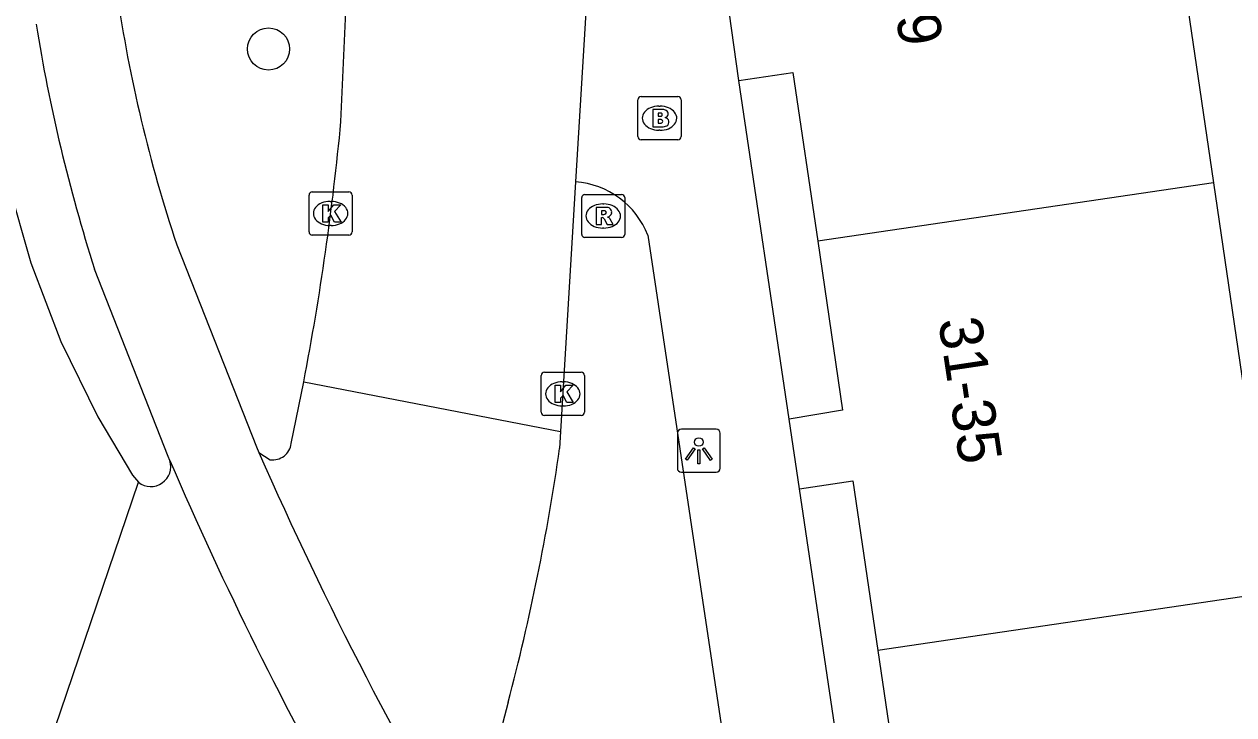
# Model space of a CAD drawing. Extents: x 159377 to 159983, y 382996 to 383595.
# Drawn here: x 159404.64 to 159432.72, y 383333.62 to 383349.64 of the extents above; entities that cross this region are included whole.
import ezdxf

# ---------------------------------------------------------------- set-up
doc = ezdxf.new("R2010")
doc.units = 0
for name, color, linetype in [('IMGEO_Boom', 7, 'Continuous'), ('IMGEO_Brandkraan', 7, 'Continuous'), ('IMGEO_Fietspad_open', 7, 'Continuous'), ('IMGEO_Kolk', 7, 'Continuous'), ('IMGEO_Lichtpunt', 7, 'Continuous'), ('IMGEO_Pand', 7, 'Continuous'), ('IMGEO_Pand_nummerreeks', 7, 'Continuous'), ('IMGEO_Rijbaan_lokaal_open', 7, 'Continuous'), ('IMGEO_Rijbaan_regionaal_gesloten', 7, 'Continuous'), ('IMGEO_Rioolput', 7, 'Continuous'), ('IMGEO_Voetpad_open', 7, 'Continuous')]:
    doc.layers.add(name, color=color, linetype=linetype)

msp = doc.modelspace()

# ---------------------------------------------------------------- linework, layer by layer
at = {"layer": 'IMGEO_Boom'}
msp.add_circle((159410.311, 383349.069), 0.489, dxfattribs=at)
at = {"layer": 'IMGEO_Brandkraan'}
for p, q in [((159418.886, 383347.038), (159418.886, 383347.89)), ((159418.961, 383347.964), (159419.813, 383347.964)), ((159419.374, 383347.744), (159419.399, 383347.744)), ((159419.887, 383347.89), (159419.887, 383347.038)), ((159419.397, 383347.184), (159419.372, 383347.184)), ((159419.813, 383346.964), (159418.961, 383346.964))]:
    msp.add_line(p, q, dxfattribs=at)
for points in [[(159418.886, 383347.038), (159418.886, 383347.89)], [(159418.961, 383347.964), (159419.813, 383347.964)], [(159419.887, 383347.89), (159419.887, 383347.038)], [(159419.234, 383347.664), (159419.234, 383347.264), (159419.447, 383347.264)], [(159419.465, 383347.664), (159419.234, 383347.664)], [(159419.413, 383347.583), (159419.359, 383347.583), (159419.359, 383347.507)], [(159419.359, 383347.507), (159419.412, 383347.507)], [(159419.421, 383347.431), (159419.359, 383347.431), (159419.359, 383347.35)], [(159419.359, 383347.35), (159419.421, 383347.35)], [(159419.813, 383346.964), (159418.961, 383346.964)]]:
    msp.add_lwpolyline(points, dxfattribs=at)
for centre, radius, start, end in [((159418.963, 383347.888), 0.0765, 91.552, 178.448), ((159418.963, 383347.888), 0.0765, 91.552, 178.448), ((159419.811, 383347.888), 0.0765, 1.552, 88.448), ((159419.811, 383347.888), 0.0765, 1.552, 88.448), ((159419.414, 383347.545), 0.0379, 267.8285, 90.9355), ((159419.469, 383347.519), 0.145, 59.4692, 91.5367), ((159419.494, 383347.566), 0.0922, 285.5137, 58.1501), ((159419.499, 383347.374), 0.105, 301.3115, 78.989), ((159419.422, 383347.39), 0.0404, 269.8759, 90.5077), ((159419.453, 383347.515), 0.251, 268.6676, 293.5347), ((159418.963, 383347.04), 0.0765, 181.552, 268.448), ((159418.963, 383347.04), 0.0765, 181.552, 268.448), ((159419.811, 383347.04), 0.0765, 271.552, 358.448), ((159419.811, 383347.04), 0.0765, 271.552, 358.448)]:
    msp.add_arc(centre, radius, start, end, dxfattribs=at)
for centre, major_axis, ratio, start_param, end_param in [((159419.373, 383347.464), (-0.387, 0.002), 0.722429, 4.712389, 7.853982), ((159419.398, 383347.464), (-0.39, 0.002), 0.717154, 1.570796, 4.712389)]:
    msp.add_ellipse(centre, major_axis=major_axis, ratio=ratio, start_param=start_param, end_param=end_param, dxfattribs=at)
at = {"layer": 'IMGEO_Fietspad_open'}
for points in [[(159408.182, 383344.528), (159410.03, 383339.844), (159410.089, 383339.709)], [(159408.022, 383339.522), (159407.982, 383339.616), (159406.273, 383343.959)]]:
    msp.add_lwpolyline(points, dxfattribs=at)
for centre, radius, start, end in [((159440.077, 383355.21), 33.636, 188.2744, 198.5159), ((159443.982, 383355.971), 39.576, 189.1999, 197.6695)]:
    msp.add_arc(centre, radius, start, end, dxfattribs=at)
at = {"layer": 'IMGEO_Kolk'}
for p, q in [((159411.251, 383344.828), (159411.251, 383345.68)), ((159411.326, 383345.754), (159412.178, 383345.754)), ((159411.739, 383345.534), (159411.764, 383345.534)), ((159412.252, 383345.68), (159412.252, 383344.828)), ((159411.762, 383344.974), (159411.737, 383344.974)), ((159412.178, 383344.754), (159411.326, 383344.754)), ((159416.716, 383341.569), (159417.568, 383341.569)), ((159416.641, 383340.643), (159416.641, 383341.495)), ((159417.129, 383341.349), (159417.154, 383341.349)), ((159417.642, 383341.495), (159417.642, 383340.643)), ((159417.152, 383340.789), (159417.127, 383340.789)), ((159417.568, 383340.569), (159416.716, 383340.569))]:
    msp.add_line(p, q, dxfattribs=at)
for points in [[(159411.251, 383344.828), (159411.251, 383345.68)], [(159411.326, 383345.754), (159412.178, 383345.754)], [(159412.252, 383345.68), (159412.252, 383344.828)], [(159411.572, 383345.454), (159411.695, 383345.454), (159411.695, 383345.303), (159411.825, 383345.454), (159411.989, 383345.454), (159411.843, 383345.303), (159411.996, 383345.054), (159411.844, 383345.054), (159411.759, 383345.218), (159411.695, 383345.151), (159411.695, 383345.054), (159411.572, 383345.054), (159411.572, 383345.454)], [(159412.178, 383344.754), (159411.326, 383344.754)], [(159416.716, 383341.569), (159417.568, 383341.569)], [(159416.641, 383340.643), (159416.641, 383341.495)], [(159417.642, 383341.495), (159417.642, 383340.643)], [(159416.962, 383341.269), (159417.085, 383341.269), (159417.085, 383341.118), (159417.215, 383341.269), (159417.379, 383341.269), (159417.233, 383341.118), (159417.386, 383340.869), (159417.234, 383340.869), (159417.149, 383341.033), (159417.085, 383340.966), (159417.085, 383340.869), (159416.962, 383340.869), (159416.962, 383341.269)], [(159417.568, 383340.569), (159416.716, 383340.569)]]:
    msp.add_lwpolyline(points, dxfattribs=at)
for centre, start, end in [((159411.328, 383345.678), 91.552, 178.448), ((159411.328, 383345.678), 91.552, 178.448), ((159412.176, 383345.678), 1.552, 88.448), ((159412.176, 383345.678), 1.552, 88.448), ((159411.328, 383344.83), 181.552, 268.448), ((159411.328, 383344.83), 181.552, 268.448), ((159412.176, 383344.83), 271.552, 358.448), ((159412.176, 383344.83), 271.552, 358.448), ((159416.718, 383341.493), 91.552, 178.448), ((159416.718, 383341.493), 91.552, 178.448), ((159417.566, 383341.493), 1.552, 88.448), ((159417.566, 383341.493), 1.552, 88.448), ((159416.718, 383340.645), 181.552, 268.448), ((159416.718, 383340.645), 181.552, 268.448), ((159417.566, 383340.645), 271.552, 358.448), ((159417.566, 383340.645), 271.552, 358.448)]:
    msp.add_arc(centre, 0.0765, start, end, dxfattribs=at)
for centre, major_axis, ratio, start_param, end_param in [((159411.738, 383345.254), (-0.387, 0.002), 0.722429, 4.712389, 7.853982), ((159411.763, 383345.254), (-0.39, 0.002), 0.717154, 1.570796, 4.712389), ((159417.128, 383341.069), (-0.387, 0.002), 0.722429, 4.712389, 7.853982), ((159417.153, 383341.069), (-0.39, 0.002), 0.717154, 1.570796, 4.712389)]:
    msp.add_ellipse(centre, major_axis=major_axis, ratio=ratio, start_param=start_param, end_param=end_param, dxfattribs=at)
at = {"layer": 'IMGEO_Lichtpunt'}
for p, q in [((159419.801, 383340.154), (159419.801, 383339.347)), ((159419.801, 383340.154), (159419.801, 383339.347)), ((159420.703, 383340.249), (159419.895, 383340.249)), ((159420.703, 383340.249), (159419.895, 383340.249)), ((159420.797, 383339.347), (159420.797, 383340.154)), ((159420.797, 383339.347), (159420.797, 383340.154)), ((159419.895, 383339.253), (159420.703, 383339.253)), ((159419.895, 383339.253), (159420.703, 383339.253))]:
    msp.add_line(p, q, dxfattribs=at)
for points in [[(159420.175, 383339.818), (159420.214, 383339.79), (159420.026, 383339.528), (159419.988, 383339.555), (159420.175, 383339.818)], [(159420.277, 383339.77), (159420.324, 383339.77), (159420.324, 383339.448), (159420.277, 383339.448), (159420.277, 383339.77)], [(159420.387, 383339.79), (159420.425, 383339.817), (159420.612, 383339.555), (159420.573, 383339.527), (159420.387, 383339.79)]]:
    msp.add_lwpolyline(points, dxfattribs=at)
msp.add_circle((159420.3, 383339.952), 0.0994, dxfattribs=at)
for centre, start, end in [((159419.895, 383340.154), 90, 180), ((159419.895, 383340.154), 90, 180), ((159420.703, 383340.154), 0, 90), ((159420.703, 383340.154), 0, 90), ((159419.895, 383339.347), 180, 270), ((159419.895, 383339.347), 180, 270), ((159420.703, 383339.347), 270, 0), ((159420.703, 383339.347), 270, 360)]:
    msp.add_arc(centre, 0.0946, start, end, dxfattribs=at)
at = {"layer": 'IMGEO_Pand'}
for points in [[(159430.851, 383355.442), (159432.244, 383345.961)], [(159421.227, 383348.338), (159421.005, 383349.935)], [(159421.227, 383348.338), (159422.482, 383348.523), (159423.058, 383344.608)], [(159432.244, 383345.961), (159423.058, 383344.608)], [(159432.244, 383345.961), (159433.639, 383336.466)], [(159423.058, 383344.608), (159423.635, 383340.693), (159422.397, 383340.483)], [(159422.633, 383338.865), (159422.397, 383340.483)], [(159422.633, 383338.865), (159423.877, 383339.048), (159424.456, 383335.114)], [(159433.639, 383336.466), (159424.456, 383335.114)], [(159424.456, 383335.114), (159425.035, 383331.18), (159423.804, 383331.003)]]:
    msp.add_lwpolyline(points, dxfattribs=at)
at = {"layer": 'IMGEO_Rijbaan_lokaal_open'}
for points in [[(159417.791, 383351.83), (159417.439, 383345.986)], [(159411.991, 383347.386), (159412.13, 383350.455), (159412.023, 383351.193)], [(159417.439, 383345.986), (159417.091, 383340.199)], [(159410.836, 383339.917), (159411.128, 383341.348)], [(159411.128, 383341.348), (159417.091, 383340.199)], [(159417.091, 383340.199), (159417.067, 383339.804)], [(159410.089, 383339.709), (159410.351, 383339.541)], [(159415.872, 383333.917), (159415.352, 383331.935)]]:
    msp.add_lwpolyline(points, dxfattribs=at)
for centre, radius, start, end in [((159348.694, 383353.352), 63.578, 349.1165, 354.61533), ((159410.41, 383339.966), 0.429, 262.0775, 353.4924), ((159489.397, 383374.406), 86.566, 203.62917, 211.26927), ((159366.975, 383346.907), 50.593, 345.122, 351.9289), ((159407.576, 383339.386), 0.467, 232.2339, 16.969), ((159487.582, 383373.724), 86.6, 203.26224, 209.57217)]:
    msp.add_arc(centre, radius, start, end, dxfattribs=at)
at = {"layer": 'IMGEO_Rijbaan_regionaal_gesloten'}
for points in [[(159396.728, 383390.154), (159399.696, 383371.074), (159399.992, 383369.176), (159401.71, 383358.95), (159403.9, 383347.897), (159404.263, 383345.982), (159404.796, 383344.107), (159405.493, 383342.287), (159406.351, 383340.537), (159407.157, 383339.182), (159407.29, 383339.017)], [(159404.942, 383332.097), (159407.29, 383339.017)]]:
    msp.add_lwpolyline(points, dxfattribs=at)
at = {"layer": 'IMGEO_Rioolput'}
for p, q in [((159417.58, 383344.769), (159417.58, 383345.621)), ((159417.655, 383345.695), (159418.507, 383345.695)), ((159418.581, 383345.621), (159418.581, 383344.769)), ((159418.068, 383345.475), (159418.093, 383345.475)), ((159418.507, 383344.695), (159417.655, 383344.695)), ((159418.091, 383344.915), (159418.066, 383344.915))]:
    msp.add_line(p, q, dxfattribs=at)
for points in [[(159417.58, 383344.769), (159417.58, 383345.621)], [(159417.655, 383345.695), (159418.507, 383345.695)], [(159418.581, 383345.621), (159418.581, 383344.769)], [(159418.169, 383345.393), (159417.917, 383345.395), (159417.917, 383344.995)], [(159418.095, 383345.314), (159418.041, 383345.314), (159418.041, 383345.233)], [(159418.041, 383345.233), (159418.093, 383345.233)], [(159417.917, 383344.995), (159418.041, 383344.995), (159418.041, 383345.157), (159418.052, 383345.157)], [(159418.099, 383345.128), (159418.17, 383344.995), (159418.31, 383344.995), (159418.245, 383345.121)], [(159418.507, 383344.695), (159417.655, 383344.695)]]:
    msp.add_lwpolyline(points, dxfattribs=at)
for centre, radius, start, end in [((159417.657, 383345.619), 0.0765, 91.552, 178.448), ((159417.657, 383345.619), 0.0765, 91.552, 178.448), ((159418.505, 383345.619), 0.0765, 1.552, 88.448), ((159418.505, 383345.619), 0.0765, 1.552, 88.448), ((159418.077, 383345.422), 0.19, 274.7715, 282.9687), ((159418.101, 383345.218), 0.0964, 77.0061, 93.1865), ((159418.115, 383345.275), 0.0378, 276.6634, 79.6772), ((159418.168, 383345.283), 0.109, 350.3612, 89.416), ((159418.166, 383345.283), 0.112, 277.5842, 350.9817), ((159418.051, 383345.104), 0.0533, 26.0293, 88.6989), ((159418.15, 383345.068), 0.108, 29.5134, 73.7905), ((159417.657, 383344.771), 0.0765, 181.552, 268.448), ((159417.657, 383344.771), 0.0765, 181.552, 268.448), ((159418.505, 383344.771), 0.0765, 271.552, 358.448), ((159418.505, 383344.771), 0.0765, 271.552, 358.448)]:
    msp.add_arc(centre, radius, start, end, dxfattribs=at)
for centre, major_axis, ratio, start_param, end_param in [((159418.067, 383345.195), (-0.387, 0.002), 0.722429, 4.712389, 7.853982), ((159418.092, 383345.195), (-0.39, 0.002), 0.717154, 1.570796, 4.712389)]:
    msp.add_ellipse(centre, major_axis=major_axis, ratio=ratio, start_param=start_param, end_param=end_param, dxfattribs=at)
at = {"layer": 'IMGEO_Voetpad_open'}
for points in [[(159422.397, 383340.483), (159421.227, 383348.338)], [(159419.116, 383344.747), (159421.821, 383326.676), (159420.246, 383325.563)], [(159423.804, 383331.003), (159422.633, 383338.865)]]:
    msp.add_lwpolyline(points, dxfattribs=at)
msp.add_arc((159417.3, 383344.043), 1.948, 21.18, 85.9046, dxfattribs=at)

# ---------------------------------------------------------------- texts
at = {"layer": 'IMGEO_Pand_nummerreeks'}
for s, rotation, p in [('25-29', 278.7641, (159424.466, 383352.469)), ('31-35', 278.5308, (159425.855, 383342.777))]:
    msp.add_text(s, height=1, rotation=rotation, dxfattribs=at).set_placement(p)

doc.saveas('drawing.dxf')
